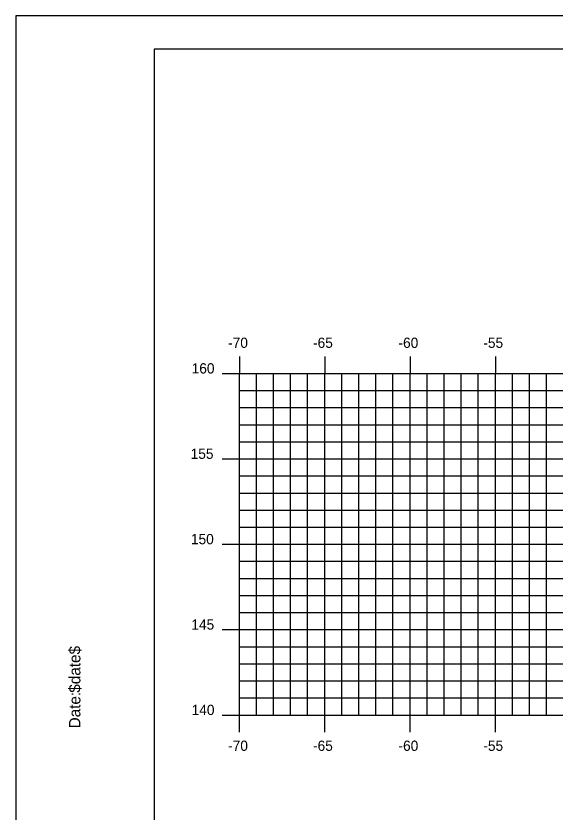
# Model space of a CAD drawing. Extents: x 1147412 to 1147582, y 608981 to 609091.
# Drawn here: x 1147411.6 to 1147443.2, y 609044.65 to 609091.28 of the extents above; entities that cross this region are included whole.
import ezdxf

# ---------------------------------------------------------------- set-up
doc = ezdxf.new("R2010")
doc.units = 0
for name, color, linetype in [('BORDER', 7, 'Continuous'), ('H_V ANNOTATION', 7, 'Continuous'), ('MAJOR', 7, 'Continuous'), ('MINOR', 7, 'Continuous'), ('PLOT BOUNDARY', 7, 'Continuous')]:
    doc.layers.add(name, color=color, linetype=linetype)

msp = doc.modelspace()

# ---------------------------------------------------------------- linework, layer by layer
at = {"layer": 'BORDER'}
msp.add_lwpolyline([(1147419.698, 608984.335), (1147579.698, 608984.335), (1147579.698, 609089.335), (1147419.698, 609089.335)], close=True, dxfattribs=at)
at = {"layer": 'MAJOR'}
for p, q in [((1147424.697, 609071.337), (1147424.697, 609070.335)), ((1147429.697, 609071.337), (1147429.697, 609070.335)), ((1147434.697, 609071.337), (1147434.697, 609070.335)), ((1147439.697, 609071.337), (1147439.697, 609070.335)), ((1147423.695, 609070.335), (1147424.697, 609070.335)), ((1147424.697, 609070.335), (1147564.697, 609070.335)), ((1147424.697, 609050.335), (1147424.697, 609070.335)), ((1147424.697, 609050.335), (1147424.697, 609070.335)), ((1147424.697, 609070.335), (1147564.697, 609070.335)), ((1147429.697, 609050.335), (1147429.697, 609070.335)), ((1147434.697, 609050.335), (1147434.697, 609070.335)), ((1147439.697, 609050.335), (1147439.697, 609070.335)), ((1147423.695, 609065.335), (1147424.697, 609065.335)), ((1147424.697, 609065.335), (1147564.697, 609065.335)), ((1147423.695, 609060.335), (1147424.697, 609060.335)), ((1147424.697, 609060.335), (1147564.697, 609060.335)), ((1147423.695, 609055.335), (1147424.697, 609055.335)), ((1147424.697, 609055.335), (1147564.697, 609055.335)), ((1147423.695, 609050.335), (1147424.697, 609050.335)), ((1147424.697, 609050.335), (1147564.697, 609050.335)), ((1147424.697, 609050.335), (1147564.697, 609050.335)), ((1147424.697, 609049.333), (1147424.697, 609050.335)), ((1147429.697, 609049.333), (1147429.697, 609050.335)), ((1147434.697, 609049.333), (1147434.697, 609050.335)), ((1147439.697, 609049.333), (1147439.697, 609050.335))]:
    msp.add_line(p, q, dxfattribs=at)
at = {"layer": 'MINOR'}
for p, q in [((1147425.697, 609050.335), (1147425.697, 609070.335)), ((1147426.697, 609050.335), (1147426.697, 609070.335)), ((1147427.697, 609050.335), (1147427.697, 609070.335)), ((1147428.697, 609050.335), (1147428.697, 609070.335)), ((1147430.697, 609050.335), (1147430.697, 609070.335)), ((1147431.697, 609050.335), (1147431.697, 609070.335)), ((1147432.697, 609050.335), (1147432.697, 609070.335)), ((1147433.697, 609050.335), (1147433.697, 609070.335)), ((1147435.697, 609050.335), (1147435.697, 609070.335)), ((1147436.697, 609050.335), (1147436.697, 609070.335)), ((1147437.697, 609050.335), (1147437.697, 609070.335)), ((1147438.697, 609050.335), (1147438.697, 609070.335)), ((1147440.697, 609050.335), (1147440.697, 609070.335)), ((1147441.697, 609050.335), (1147441.697, 609070.335)), ((1147442.697, 609050.335), (1147442.697, 609070.335)), ((1147424.697, 609069.335), (1147564.697, 609069.335)), ((1147424.697, 609069.335), (1147425.699, 609069.335)), ((1147424.697, 609068.335), (1147564.697, 609068.335)), ((1147424.697, 609068.335), (1147425.699, 609068.335)), ((1147424.697, 609067.335), (1147564.697, 609067.335)), ((1147424.697, 609067.335), (1147425.699, 609067.335)), ((1147424.697, 609066.335), (1147564.697, 609066.335)), ((1147424.697, 609066.335), (1147425.699, 609066.335)), ((1147424.697, 609064.335), (1147564.697, 609064.335)), ((1147424.697, 609064.335), (1147425.699, 609064.335)), ((1147424.697, 609063.335), (1147564.697, 609063.335)), ((1147424.697, 609063.335), (1147425.699, 609063.335)), ((1147424.697, 609062.335), (1147564.697, 609062.335)), ((1147424.697, 609062.335), (1147425.699, 609062.335)), ((1147424.697, 609061.335), (1147564.697, 609061.335)), ((1147424.697, 609061.335), (1147425.699, 609061.335)), ((1147424.697, 609059.335), (1147564.697, 609059.335)), ((1147424.697, 609059.335), (1147425.699, 609059.335)), ((1147424.697, 609058.335), (1147564.697, 609058.335)), ((1147424.697, 609058.335), (1147425.699, 609058.335)), ((1147424.697, 609057.335), (1147564.697, 609057.335)), ((1147424.697, 609057.335), (1147425.699, 609057.335)), ((1147424.697, 609056.335), (1147564.697, 609056.335)), ((1147424.697, 609056.335), (1147425.699, 609056.335)), ((1147424.697, 609054.335), (1147564.697, 609054.335)), ((1147424.697, 609054.335), (1147425.699, 609054.335)), ((1147424.697, 609053.335), (1147564.697, 609053.335)), ((1147424.697, 609053.335), (1147425.699, 609053.335)), ((1147424.697, 609052.335), (1147564.697, 609052.335)), ((1147424.697, 609052.335), (1147425.699, 609052.335)), ((1147424.697, 609051.335), (1147564.697, 609051.335)), ((1147424.697, 609051.335), (1147425.699, 609051.335))]:
    msp.add_line(p, q, dxfattribs=at)
at = {"layer": 'PLOT BOUNDARY'}
msp.add_lwpolyline([(1147411.604, 608981.276), (1147581.604, 608981.276), (1147581.604, 609091.276), (1147411.604, 609091.276)], close=True, dxfattribs=at)

# ---------------------------------------------------------------- texts
at = {"layer": 'BORDER'}
for s, p in [('$date$', (1147415.383, 609051.64)), ('Date:', (1147415.383, 609049.552))]:
    msp.add_text(s, height=0.6696, rotation=90, dxfattribs=at).set_placement(p)
at = {"layer": 'H_V ANNOTATION'}
for s, p in [('-70', (1147424.039, 609071.835)), ('-65', (1147429.015, 609071.835)), ('-60', (1147434.023, 609071.835)), ('-55', (1147438.994, 609071.835)), ('160', (1147421.902, 609070.335)), ('155', (1147421.843, 609065.335)), ('150', (1147421.859, 609060.335)), ('145', (1147421.886, 609055.335)), ('140', (1147421.902, 609050.335)), ('-70', (1147424.039, 609048.235)), ('-65', (1147429.015, 609048.235)), ('-60', (1147434.023, 609048.235)), ('-55', (1147438.994, 609048.235))]:
    msp.add_text(s, height=0.6, dxfattribs=at).set_placement(p)
at = {"layer": 'MAJOR'}
msp.add_text('-', height=0.006, dxfattribs=at).set_placement((1147424.693, 609050.335))

doc.saveas('drawing.dxf')
